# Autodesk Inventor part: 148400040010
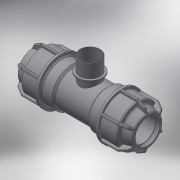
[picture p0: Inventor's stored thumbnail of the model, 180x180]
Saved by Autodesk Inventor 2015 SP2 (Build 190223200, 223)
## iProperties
Created: 2017-08
Part Number: 148400040010
Material: Generic
Description: PLASSON L.14 TEE MALE ADAPTOR (SILVER) 40-1"-40
Document SubType Name: Modeling
Designer: KIM
Density: 1 g/cm^3
Appearance: Default
Author: KIM
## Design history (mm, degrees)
derived "148400.ipt"
feature "Solid1::148400.ipt"
feature "Solid2::148400.ipt"
tag "TaggingFeature1"
body "Solid1"
body "Solid2"
other parameters: "d2" = 62, "d4" = 15 deg, "d5" = 40.92, "d6" = 13.5036, "d10" = 73, "d16" = 40.8, "d17" = 3.1, "d22" = 64, "d24" = 3.1, "d25" = 65.7, "d26" = 54.75, "d27" = 3.1, "d28" = 135 deg, "d29" = 1.86, "d31" = 2, "d46" = 150 deg, "d49" = 3.65, "d50" = 0, "d58" = 1.2, "d61" = 360 deg, "d63" = 36, "d64" = 86.5, "d80" = 57.6, "d81" = 3.2, "d84" = 3.1, "d94" = 65, "d96" = 33.249, "d108" = 1.2, "d111" = 0, "d113" = 32, "d114" = 39.8988, "d116" = 2, "d117" = 33.249, "R_" = 33.249, "E_" = 73, "H_" = 173, "l_" = 62, "A_" = 65
